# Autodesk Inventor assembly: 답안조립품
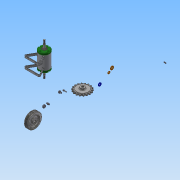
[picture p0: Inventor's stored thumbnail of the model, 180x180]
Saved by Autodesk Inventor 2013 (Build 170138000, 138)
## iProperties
Created: 2016-03
Part Number: 답안조립품
Document SubType Name: Assembly
Designer: Administrator
Author: Administrator
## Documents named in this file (16)
- C:\Users\Administrator\Desktop\460308V1026\답안조립품.iam
- C:\Users\Administrator\Desktop\460308V1026\본체.ipt
- C:\Users\Administrator\Desktop\460308V1026\V벨트풀리.ipt
- C:\Users\Administrator\Desktop\460308V1026\너트 M 8.ipt
- C:\Users\Administrator\Desktop\460308V1026\니플 M 6 x 0.75.ipt
- C:\Users\Administrator\Desktop\460308V1026\베어링 15 x 32 x 9.ipt
- C:\Users\Administrator\Desktop\460308V1026\볼트 M 6 x 8.ipt
- C:\Users\Administrator\Desktop\460308V1026\볼트 M4 x 12.ipt
- C:\Users\Administrator\Desktop\460308V1026\스프로킷.ipt
- C:\Users\Administrator\Desktop\460308V1026\스프링와셔 8.ipt
- C:\Users\Administrator\Desktop\460308V1026\오일 실 15 25 7.ipt
- C:\Users\Administrator\Desktop\460308V1026\와셔 6x11.5.ipt
- C:\Users\Administrator\Desktop\460308V1026\와셔 8x17.ipt
- C:\Users\Administrator\Desktop\460308V1026\축.ipt
- C:\Users\Administrator\Desktop\460308V1026\커버.ipt
- C:\Users\Administrator\Desktop\460308V1026\키 3 x 3 x 12.ipt
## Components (4 placed, 3 different names)
1. V벨트풀리:1
2. KS B 2023 6002 - 15 x 32 x 9:1
3. ISO 4762 M4 x 12:1
4. KS B 2023 6002 - 15 x 32 x 9:2
